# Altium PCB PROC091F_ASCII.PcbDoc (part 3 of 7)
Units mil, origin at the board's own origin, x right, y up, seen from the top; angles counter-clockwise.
Board outline 3590.95 x 906.17 mil, 8 copper layers (Top Layer, GND1, Sig1, PWR1, PWR2, Sig2, GND2, Bottom Layer), stack 63.146 mil thick; 420 components, 316 nets, 1432 pads, 774 vias.
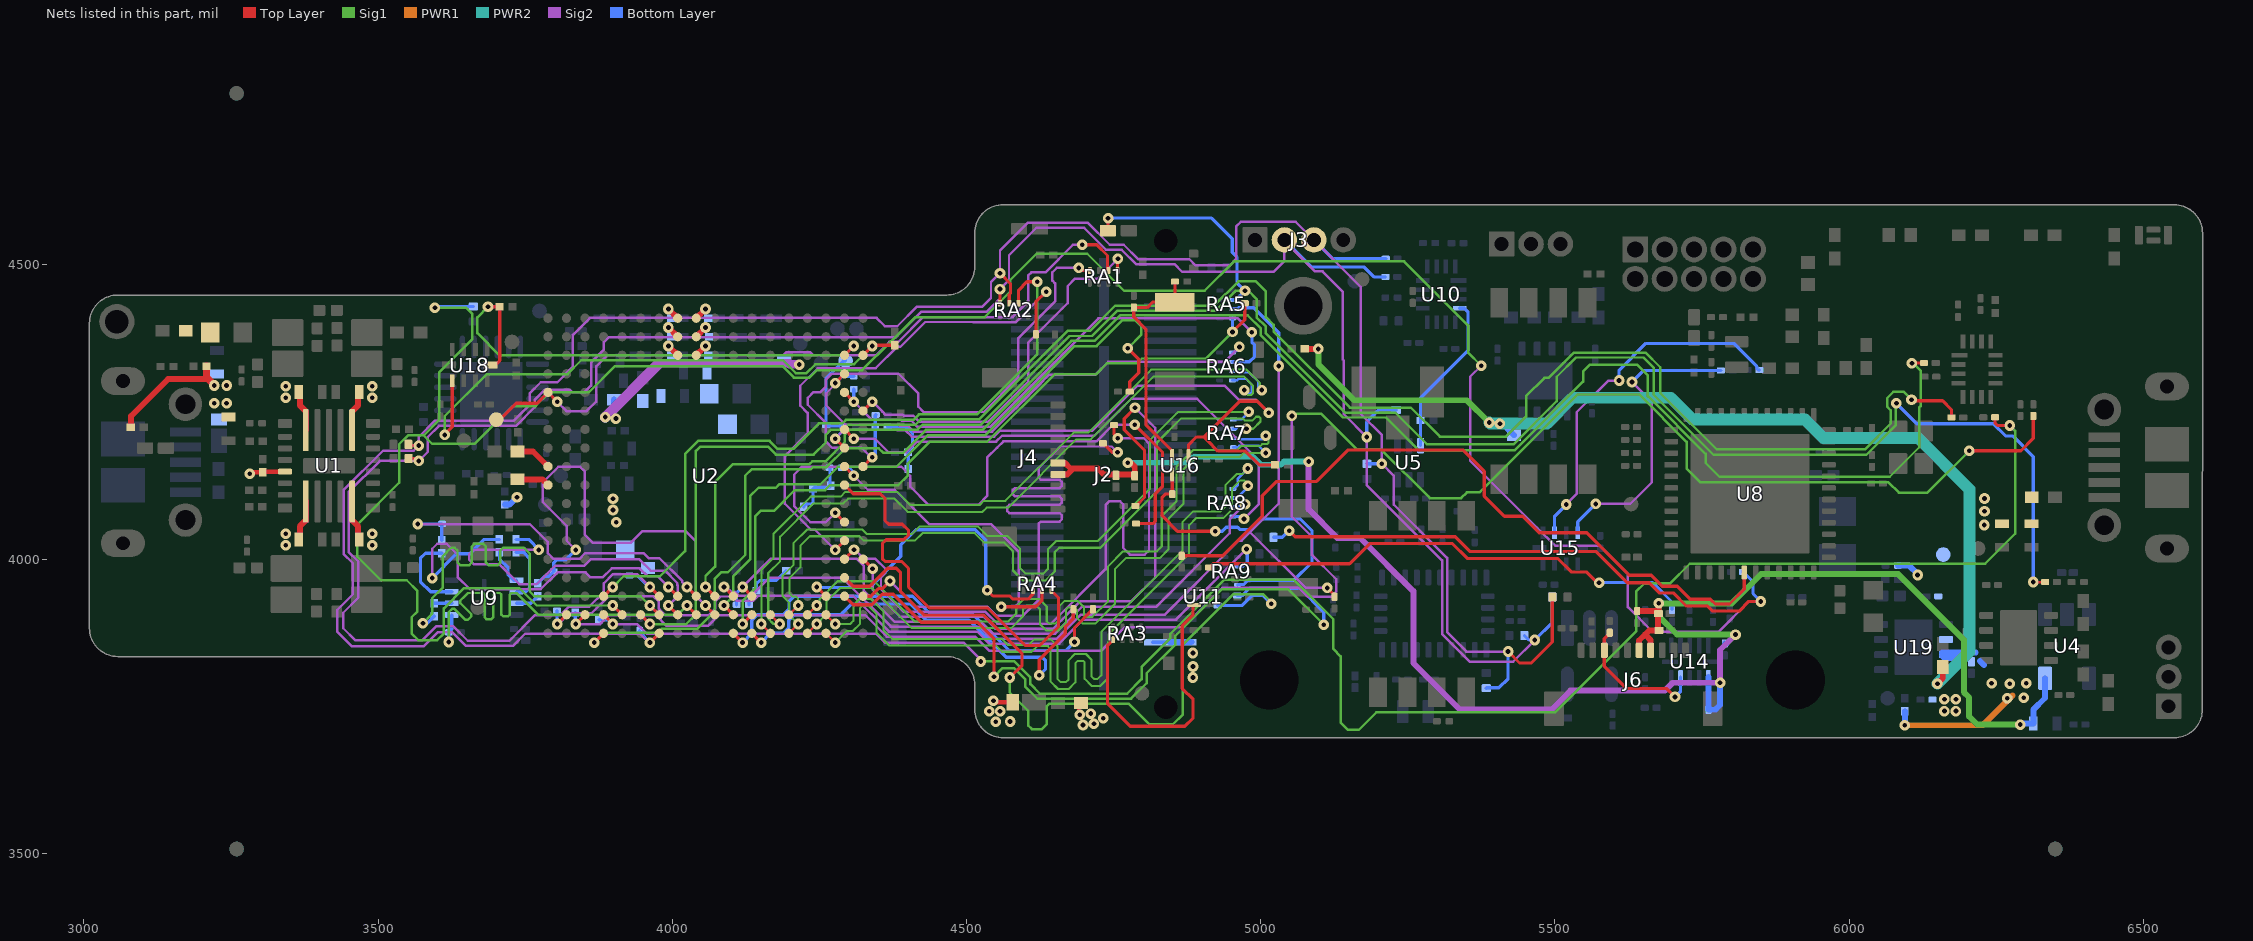
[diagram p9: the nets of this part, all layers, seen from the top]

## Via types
v1: diameter 18, hole 8, Top Layer to Bottom Layer, tented both sides, 737 vias
v2: diameter 19.68, hole 7.87, Top Layer to Bottom Layer, tented both sides, 36 vias
v3: diameter 17, hole 8, Top Layer to Bottom Layer, tented both sides, 1 vias

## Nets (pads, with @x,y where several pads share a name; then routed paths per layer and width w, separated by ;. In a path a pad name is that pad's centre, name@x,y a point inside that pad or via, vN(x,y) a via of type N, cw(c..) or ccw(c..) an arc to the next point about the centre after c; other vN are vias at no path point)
3V0: C7.1 C15.1 C16.1 C115.1 C116.1 C118.1 J4.6 J4.7 J6.6 J6.7 R79.2 R181.2 U4.5 U14.1 | length 3021.3
  Top Layer w10: J4.7@4653.44,4143.81 4671.13,4143.81 4681.23,4153.91 ; J4.6@4653.44,4163.49 J4.6@4655.33,4163.49 4667.18,4163.49 4676.77,4153.91 4681.23,4153.91 ; v1(4774.17,4163.77) 4779.19,4163.77 4785.89,4157.08 4785.89,4142.64 4785.08,4143.44 4733.74,4143.44 4723.27,4153.91 4681.23,4153.91 ; R181.2@5639.79,3911.66 C115.1@5670.49,3911.66 ; J6.6@5643.01,3845.06 5643.01,3861.54 5653.24,3871.77 ; J6.7@5662.69,3842.06 5662.69,3862.32 5653.24,3871.77 ; C115.1@5676.11,3907.2 C115.1@5674.96,3907.2 ; v1(5676.18,3924.73) 5676.18,3908.42 C115.1@5674.96,3907.2 ; 5653.24,3871.77 5660.21,3878.74 5675.67,3878.74 5674.96,3879.45 C115.1@5674.96,3907.2
  Sig1 w10: v1(5806.88,3871.77) 5707.39,3871.77 5676.18,3902.98 v1(5676.18,3924.73) 5800.43,3924.73 5850.17,3974.46 6083.34,3974.46 6195,3862.8 6195,3773.9 6203.8,3765.1 6203.8,3732.72 6217.72,3718.79 v1(6290.97,3718.79)
  PWR2 w10: v1(4774.17,4163.77) 4876.32,4163.77 4886.45,4173.91 4986.43,4173.91 4999.95,4160.4 5034.48,4160.4 5039.83,4165.74 v1(5081.47,4165.74)
  Sig2 w10: v1(5081.47,4165.74) 5081.47,4084.56 5130.11,4035.92 5168.92,4035.92 5259.37,3945.46 5259.37,3823.46 5338.37,3744.46 5494.41,3744.46 5526.41,3776.46 5686.78,3776.46 5700.1,3789.79 v1(5780.63,3789.79) 5780.63,3845.63 v1@5806.82,3871.82
  Bottom Layer w10: U14.1@5760.73,3799.77 5760.73,3764.35 5760.69,3764.32 C118.1@5760.69,3743.88 5772.53,3743.88 5780.63,3751.98 v1(5780.63,3789.79) ; R79.2@5788.67,3856.48 5791.58,3856.48 v1(5806.88,3871.77) ; v1(6290.97,3718.79) 6292.97,3720.79 C7.1@6312.97,3720.79 6312.97,3743.97 6332.97,3763.97 U4.5@6332.97,3797.49
5V_HD_IN: C128.1 J2.2 R20.1 U19.8 | length 106.4
  Bottom Layer w6: J2.2@4816.76,3859.07 J2.2@4846.16,3859.07
  Bottom Layer w10: J2.2@4846.16,3859.07 J2.2@4882.13,3859.07 ; R20.1@6082.89,3988.94 6102.24,3988.94 6116.23,3974.95 v1(6116.23,3973.04)
  other v1: 6161.94,3741.7 6181.41,3741.74 6161.94,3761.63 6181.41,3761.68 4884.84,3798.74 4885,3817.45 4884.84,3840.39
5V_IN: C1.2 C4.1 C30.1 C50.1 C51.1 C52.1 C53.1 D1.1 D2.1 FL3.2 FL12.2 R39.1 R50.2 R64.1 R107.1 U1.9 U1.13 U1.18 U1.22 U1.26 | length 2301.2
  Top Layer w8: v1(3282,4145) 3284.5,4147.5 C30.1@3304,4147.5 3305.18,4148.68 U1.18@3341.81,4148.68 ; v1@4551.43,3756.69 4551.24,3756.88 D2.1@4578.64,3756.88
  Top Layer w10: R39.1@3079.65,4222.86 3080.01,4222.86 3080.01,4242.86 3142.95,4305.8 3209.86,4305.8 ; C52.1@3367.11,4033.27 3367.11,4055.68 3377.24,4065.81 U1.22@3377.24,4097.89 ; C51.1@3367.11,4283.77 3367.11,4261.36 3377.24,4251.23 U1.13@3377.24,4219.15 ; U1.26@3455.98,4097.89 3455.98,4065.81 3466.11,4055.68 C53.1@3466.11,4033.27 ; U1.9@3455.98,4219.15 3455.98,4251.23 3466.11,4261.36 C50.1@3466.11,4283.77 ; R107.1@5074.64,4357.18 v1@5098.17,4357.18 ; v1(5098,4357.17) v1@5098.15,4357.17 ; v1(6150,3788) 6159,3797 FL3.2@6159,3816.31
  Top Layer w12: R50.2@3208.43,4327.73 3208.43,4309.08 v1@3222.57,4294.93
  Sig1 w10: v1(5098,4357.17) 5098,4331 5159,4270 5350.21,4270 v1(5388.21,4232)
  PWR2 w20: v1(5388.21,4232) 5389.98,4230.23 v1(5406.56,4230.23) 5486,4230.23 5529.77,4274 5697,4274 5734,4237 5925,4237 5956,4206 6117,4206 6204.39,4118.61 6204.39,3842.39 v1(6150,3788)
  Bottom Layer w10: R64.1@3715.38,4092.76 3723.59,4092.76 v1(3736.09,4105.26) ; v1@5408.87,4232 FL12.2@5430.41,4210.46
  other v1: 4549.8,3723.5 4574.04,3724.04 4557.1,3741.4 4538.79,3741.55 4545.8,3759.4 3343.32,4023.52 3489.9,4023.52 3343.32,4043.02 3489.9,4043.02 3221.57,4264.93 3242.57,4264.93 3343.32,4274.02 3489.9,4274.02 3343.32,4293.52 3489.9,4293.52 3221.57,4294.93 3242.57,4294.93
5V_IN_B: C42.2 C122.1 C127.1 FL14.2 TP4.1 U19.6
  other v1: 6229.39,4058 6230,4081.54 6230,4103
5V_IN_SW: C129.1 FL11.1 R27.1 U19.7 | length 387.8
  Top Layer w6: v1@4691.08,3733.43 FL11.1@4691.08,3755.5
  PWR1 w10: v1(6094.58,3717.68) 6227.1,3717.68 6277.87,3768.45
  Bottom Layer w10: v1(6094.58,3717.68) R27.1@6094.58,3741.52 ; U19.7@6157.3,3840.2 6158.2,3841.1 6198.3,3841.1 ; U19.7@6157.5,3836.1 6162.01,3831.6 6191.4,3831.6 6186.3,3836.69 U19.7@6161.94,3836.69 ; 6200,3839.4 6198.3,3841.1 ; 6215.1,3841.1 6198.3,3841.1 ; 6222.1,3826.76 6228.92,3819.94
  other v1: 4698.06,3717.99 4716.52,3720.32 4732.55,3729.58 4692.44,3735.48 4711.02,3737.49 6268.5,3763.5 6296.5,3764.5 6273,3788 6242,3789 6301,3789
ALERT: R38.1 U5.3 U10.4 | length 277.2
  Bottom Layer w5.5: U5.3@5271.66,4192.9 R38.1@5271.66,4235.46 5271.66,4274.01 5352.46,4354.8 5352.46,4419.82 5346.17,4426.11 U10.4@5338.3,4426.11
AR_1P0_RF1: C78.1 C79.1 C80.1 C81.1 L12.2 U2.J16 U2.J17 U2.J18 | length 66.8
  Top Layer w10: U2.J16@4040.73,4346.33 v1(4056.48,4362.08) ; U2.J17@4040.73,4377.83 v1(4056.48,4393.58) ; U2.J18@4040.73,4409.33 v1(4056.48,4425.07)
AR_1P0_RF2: C82.1 C83.1 C84.1 C85.1 FL1.1 L14.2 U2.H16 U2.H17 U2.H18 | length 66.8
  Top Layer w10: v1(3993.49,4362.08) U2.H16@4009.24,4346.33 ; v1(3993.49,4393.58) U2.H17@4009.24,4377.83 ; v1(3993.49,4425.07) U2.H18@4009.24,4409.33
AR_1P2: FL6.1 L13.2
AR_1V4_APLL: C90.1 U2.A10 | length 62.3
  Top Layer w10: C90.1@3737.06,4182.85 3763.27,4182.85 U2.A10@3788.76,4157.36
AR_1V4_SYNTH: C89.1 U2.A9 | length 55.5
  Top Layer w10: C89.1@3737.19,4135.45 3779.18,4135.45 U2.A9@3788.76,4125.86
AR_1V8: FL8.1 FL9.1 FL10.1 L11.2 | length 404.6
  Sig2 w15: 3975.42,4330.59 3976.08,4331.25 ; 3976.08,4332.75 4199.24,4332.75 ; 4199.24,4331.25 4199.33,4331.16 4215.39,4331.16 v1(4215.96,4330.59)
  Sig2 w18: v1(3886.15,4241.31) 3975.42,4330.59
  Bottom Layer w10: v1(3886.15,4241.31) 3888.61,4241.31 3901,4253.7 FL9.1@3901,4271
  other v1: 3904.64,4062.7 3899.25,4083.38 3899.25,4102.38 3904.29,4238.76
AR_BSS_LOGGER: RA2.2 U2.D3 | length 1197.9
  Top Layer w5.5: U2.D3@3883.25,3936.89 v1(3899,3952.63) ; RA2.2@4588.48,4434.82 4588.48,4456.94 4602.74,4471.2 v1(4620,4471.2)
  Sig1 w4.2: v1(3899,3952.63) 3917.29,3970.92 3979.16,3970.92 4021.78,4013.55 4021.78,4178.81 4043.81,4200.84 4165.39,4200.84 4179.07,4187.16 4205.95,4187.16 4249.28,4230.49 4288.94,4230.49 4295.15,4236.7 4409.94,4236.7 4419.12,4245.88 4517.88,4245.88 4620,4348 v1(4620,4471.2)
AR_CS1: R9.2 R139.2 U2.C2 | length 3331.6
  Top Layer w5.5: v1(3836.01,3889.64) U2.C2@3851.76,3905.39 ; v1(6204,4184) 6292,4184 6313,4205 R139.2@6313,4242.98
  Sig1 w4.2: v1(5053,4243.3) 5057,4247.3 5102.7,4247.3 5164.32,4185.68 5205.42,4185.68 5287.4,4103.7 5340.7,4103.7 5350.29,4113.29 5371.69,4113.29 5538.09,4279.7 5643.45,4279.7 5723.89,4199.26 5723.89,4154.03 5747.43,4130.49 6066.87,4130.49 6084.43,4112.93 6132.93,4112.93 v1(6204,4184)
  Sig2 w4.2: v1(3836.01,3889.64) 3877.36,3889.64 3892.66,3904.94 3972.04,3904.94 3990.46,3886.52 4060.75,3886.52 4079.18,3904.94 4328.02,3904.94 4364.57,3868.39 4514.72,3868.39 4539.2,3843.9 4728.57,3843.9 4768.67,3884 4868,3884 4935,3951 5064.76,3951 5080.06,3935.7 5119.48,3935.7 5128.45,3944.66 5128.45,3965.78 5087,4007.23 5087,4038 5053,4072 v1(5053,4243.3)
  Bottom Layer w5.5: R9.2@3835,3909.17 3835,3890.65 v1(3836.01,3889.64)
AR_CS1_60PIN: RA3.1 U11.3 | length 486.5
  Top Layer w5.5: RA3.1@4749.31,3863.01 4739.81,3853.51 4739.81,3754.36 4778.08,3716.09 4871.09,3716.09 4885,3730 4885,3761.65 4866.65,3780 4866.65,3886.76 4884.99,3905.09 U11.3@4884.99,3921.94
AR_CS1_BT: R105.2 U8.30 | length 1222.9
  Top Layer w5.5: R105.2@4865.78,4005.59 4935.59,4005.59 5002.56,4072.56 5002.56,4107.46 5027.1,4132 5094.9,4132 5148.45,4185.56 5343.25,4185.56 5379.8,4149.01 5379.8,4107.15 5414.23,4072.71 5445.66,4072.71 5473.46,4044.92 5554.09,4044.92 5626.54,3972.46 5663.74,3972.46 5682.22,3953.98 5707.75,3953.98 5730.02,3931.71 5764.22,3931.71 5772.3,3923.63 5796.62,3923.63 5821.73,3948.74 U8.30@5821.73,3977.25
AR_CS1_LCD: R76.2 R106.2 | length 857.3
  Top Layer w5.5: R106.2@4912.37,3985.56 4918.93,3992.13 5151.04,3992.13 5185.33,4026.43 5325.91,4026.43 5351.12,4001.21 5504.41,4001.21 5527.37,3978.25 5553.48,3978.25 5571.73,3960 v1(5575,3960)
  Bottom Layer w5.5: v1(5575,3960) 5666.02,3960 5698.97,3927.05 R76.2@5698.97,3914.47
AR_CS1_LCD_T: J6.3 R183.1 U14.4 | length 239.1
  Top Layer w5.5: R183.1@5593.19,3873.82 5583.95,3864.58 J6.3@5583.95,3845.06 5583.95,3818.24 5622.3,3779.89 5689.95,3779.89 v1(5704.03,3765.81)
  Bottom Layer w5.5: v1(5704.03,3765.81) 5713.48,3775.26 U14.4@5713.48,3797.8 U14.4@5713.48,3799.77
AR_DMM_CLK: R11.1 U2.U3 | length 1270.4
  Top Layer w5.5: U2.U3@4292.7,3936.89 4307.32,3922.26 4338.99,3922.26 4357.08,3940.36 4375.65,3940.36 4423.2,3892.8 4518.93,3892.8 4546.57,3865.15 v1(4546.57,3799.81)
  Sig1 w4.2: v1(4546.57,3799.81) 4561.46,3814.7 4580.9,3814.7 4600.07,3795.53 4600.07,3782.93 4620.19,3762.81 4779.81,3762.81 4806,3789 4806,3806 4855,3855 4855,3869.71 4934.29,3949 5046.57,3949 v1(5107.05,3888.52)
  Bottom Layer w5.5: R11.1@4960.02,3937.94 4968.46,3937.94 4980.77,3950.25 5066.75,3950.25 5107.05,3909.95 v1(5107.05,3888.52)
AR_DMM_SYNC: R10.1 U2.U4 | length 1283.7
  Top Layer w5.5: U2.U4@4292.7,3968.38 4307.32,3953.76 4335.57,3953.76 4366.31,3984.5 4380.6,3984.5 4388,3977.1 4388,3944.27 4427.07,3905.2 4528.29,3905.2 4594.49,3839 4594.49,3819.69 v1(4573.55,3798.74)
  Sig1 w4.2: v1(4573.55,3798.74) 4573.55,3773.45 4605,3742 4605,3717 4611,3711 4628,3711 4636,3719 4636,3749.41 4641,3754.41 4775.59,3754.41 4810.94,3719.06 4850.56,3719.06 4867.66,3736.15 4867.66,3854.66 4953.6,3940.6 5004,3940.6 5018,3926.6 v1(5018,3924)
  Bottom Layer w5.5: R10.1@4927.02,3921 4967.78,3921 4985.53,3938.75 5003.25,3938.75 v1(5018,3924)
AR_DP0: R88.1 U2.U7 | length 1102
  Top Layer w5.5: v1(4276.95,4078.62) U2.U7@4292.7,4062.87 ; v1(4786.14,4228.21) 4833.25,4181.1 4833.25,4123.66 4820.91,4111.32 4820.91,4064.23 4817.01,4060.33 R88.1@4789.21,4060.33
  Sig2 w4.2: v1(4276.95,4078.62) 4261.23,4062.89 4234.4,4062.89 4207.08,4090.21 4207.08,4100.94 4207.08,4111.59 4207.08,4143.33 4220.78,4157.04 4389.09,4157.04 4404.46,4141.67 4404.46,4123.28 4435.52,4092.22 4519.97,4092.22 4535.14,4107.38 4535.14,4172.74 4551.69,4189.3 4551.95,4189.3 4562.68,4200.02 4721.12,4200.02 4749.31,4228.21 v1(4786.14,4228.21)
AR_DP1: R130.1 U2.U6 | length 924.9
  Top Layer w5.5: v1(4276.95,4015.63) U2.U6@4292.7,4031.37 ; R130.1@4617.95,4383.18 4617.95,4437.33 4635.19,4454.56 v1(4635.35,4454.4)
  Sig2 w4.2: v1(4276.95,4015.63) 4242.74,4049.83 4235.58,4049.83 4191.3,4094.11 4191.3,4175.11 4230,4213.81 4230,4248.45 4217.54,4260.92 4217.54,4294.54 4247.25,4324.25 4345.44,4324.25 4381.77,4360.58 4387.52,4360.58 4429.85,4402.91 4475.18,4402.91 4511.29,4402.91 4511.35,4402.85 4583.81,4402.85 v1(4635.35,4454.4)
AR_DP2: R132.1 U2.V5 | length 1098.3
  Top Layer w5.5: U2.V5@4324.64,3999.43 v1(4340.39,3983.68) ; v1(4786.37,4257.18) 4768.03,4238.84 4768.03,4219.51 4802.49,4185.05 4802.49,4104.7 R132.1@4788.36,4090.57
  Sig2 w4.2: v1(4340.39,3983.68) 4340.39,3948.49 4386.9,3901.99 4528.64,3901.99 4548.94,3881.69 4646.96,3881.69 4694,3928.72 4780.31,3928.72 4820.7,3969.11 4820.7,4222.85 v1(4786.37,4257.18)
AR_DP3: R133.1 U2.U5 | length 1103.4
  Top Layer w5.5: U2.U5@4293.15,4000.33 v1(4308.9,4016.07) ; R133.1@4750.69,4227.63 4750.69,4211.75 v1(4756.94,4205.49)
  Sig2 w4.2: v1(4308.9,4016.07) 4310.02,4016.07 4325.77,4000.33 4345.39,4000.33 4362,3983.71 4362,3976.46 4354.7,3969.16 4354.7,3949.12 4393.43,3910.39 4532.11,3910.39 4552.41,3890.09 4643.49,3890.09 4736.28,3982.88 4736.28,4091.85 4742.4,4097.98 4761.3,4097.98 4766.06,4093.22 4766.06,4019.21 4777.65,4007.61 4802.88,4007.61 4810.15,4014.88 4810.15,4196.59 4801.24,4205.49 v1(4756.94,4205.49)
AR_DP4: R135.1 U2.V3 | length 1157.1
  Top Layer w5.5: U2.V3@4324.2,3936.89 4337.35,3936.89 4350.32,3949.86 4357.03,3949.86 v1(4370,3962.82) ; R135.1@4732.07,4196.8 4747.41,4181.46 v1(4756.8,4181.46)
  Sig2 w4.2: v1(4370,3962.82) 4414.04,3918.79 4535.59,3918.79 4550.54,3903.84 4595.78,3903.84 4622.63,3930.69 4622.63,4029.66 4622.63,4060.28 4626.18,4063.83 4658.3,4063.83 4661.85,4067.38 4661.85,4074.48 4658.3,4078.03 4622.63,4078.03 4572.87,4078.03 4569.32,4081.58 4569.32,4088.68 4572.87,4092.23 4622.63,4092.23 4658.15,4092.23 4661.7,4095.78 4661.7,4102.88 4658.15,4106.43 4622.63,4106.43 4582.47,4106.43 4578.92,4109.98 4578.92,4117.08 4582.47,4120.63 4622.63,4120.63 4658.3,4120.63 4661.85,4124.18 4661.85,4131.28 4658.3,4134.83 4626.18,4134.83 4622.63,4138.38 4622.63,4141.93 4622.63,4154.35 4659.61,4191.33 4746.93,4191.33 v1(4756.8,4181.46)
AR_DP5: R137.1 U2.M1 | length 745.7
  Top Layer w5.5: U2.M1@4135.22,3873.89 v1(4150.97,3858.15) ; v1(4623.77,3802.58) 4623.77,3829.27 4667.89,3873.39 4667.89,3884.63 4681.54,3898.29 R137.1@4681.54,3914.69
  Bottom Layer w5.5: v1(4150.97,3858.15) 4166.72,3873.9 4176.3,3873.9 4176.39,3873.99 4188.95,3873.99 4198.11,3883.16 4198.11,3895.93 4207.67,3905.49 4286.39,3905.49 4304.8,3923.9 4404.12,3923.9 4431.61,3896.41 4504.41,3896.41 4567.49,3833.32 4628.48,3833.32 4634.4,3827.4 4634.4,3813.21 v1(4623.77,3802.58)
AR_DP6: R138.1 U2.L2 | length 1153.9
  Top Layer w5.5: v1(4087.98,3921.14) U2.L2@4103.72,3905.39 ; v1(4774.14,4358.34) 4792.59,4339.89 4792.59,4316.78 4777.4,4301.59 R138.1@4777.4,4284.46
  Sig1 w4.2: v1(4087.98,3921.14) 4103.28,3936.44 4103.28,3970.27 4132.4,3999.39 4132.4,4107 4146.71,4121.31 4176,4121.31 4181.7,4127.01 4251.5,4127.01 4281.4,4156.91 4380.91,4156.91 4434.86,4210.86 4532.1,4210.86 4683.32,4362.08 4720.96,4362.08 4764.48,4405.6 4787.14,4405.6 4797.34,4395.41 4797.34,4381.53 v1(4774.14,4358.34)
AR_DP7: R140.1 U2.L1 | length 752
  Top Layer w5.5: U2.L1@4103.72,3873.89 v1(4119.47,3858.15) ; v1(4683.56,3859.2) 4683.56,3883.42 R140.1@4714.81,3914.68
  Bottom Layer w5.5: v1(4119.47,3858.15) 4135.23,3873.9 4135.23,3896.22 4144.4,3905.39 4188.85,3905.39 4198.31,3914.85 4198.31,3927.62 4207.48,3936.79 4408.21,3936.79 4437.09,3907.91 4509.17,3907.91 4572.26,3844.82 4669.18,3844.82 v1(4683.56,3859.2)
AR_GPIO_0: R66.1 RA5.8 U2.M2 | length 1247.4
  Top Layer w5.5: v1(4119.47,3889.64) U2.M2@4135.22,3905.39 ; v1(4952,4386) 4972.88,4406.88 R66.1@4972.88,4434.77
  Sig1 w4.2: v1(4119.47,3889.64) 4119.47,3928.77 4140.8,3950.1 4140.8,4072.57 4150.14,4081.91 4172.91,4081.91 4208.14,4117.14 4259.64,4117.14 4268.36,4125.86 4384.06,4125.86 4400.5,4142.3 4400.5,4162.2 4437.86,4199.56 4535.36,4199.56 4649.8,4314 4719.9,4314 4738.7,4332.8 4789.7,4332.8 4797.8,4340.9 4906.9,4340.9 v1(4952,4386)
  Bottom Layer w5.5: v1(4952,4386) 4952,4408.75 RA5.8@4952.34,4409.09
AR_GPIO_1: R129.2 RA5.7 U2.L3 | length 1696.1
  Top Layer w5.5: v1(4087.98,3952.63) U2.L3@4103.72,3936.89 ; v1(5113.15,3951) R129.2@5125.2,3938.94
  Sig2 w4.2: v1(4087.98,3952.63) 4091.71,3952.63 4099.51,3944.84 4105.63,3944.84 4113.14,3937.33 4133.62,3937.33 4164.22,3967.93 4288.79,3967.93 4371.53,3885.19 4521.68,3885.19 4541.98,3864.89 4653.92,3864.89 4694.64,3905.61 4837.03,3905.61 4962.72,4031.3 4967.81,4031.3 4982.07,4045.57 ; v1@5030.5,4328.13 5030.5,4093.99 4982.07,4045.57 ; v1(5113.15,3951) 5076.64,3951 4982.07,4045.57
  Bottom Layer w5.5: RA5.7@4952.34,4424.84 4953.03,4425.54 4960.71,4425.54 4962.27,4427.09 4988.12,4427.09 5030.72,4384.49 v1(5030.72,4328.13)
AR_GPIO_2: LD3.1 R115.1 RA5.6 U2.K3 | length 3607.2
  Top Layer w4.2: v1(6312.97,3961) R115.1@6332.97,3961
  Top Layer w5.5: v1(4056.48,3952.63) U2.K3@4072.23,3936.89 ; LD3.1@4740.42,4558.15 4740.42,4579.31 v1(4740.56,4579.45)
  Sig1 w4.2: v1(4056.48,3952.63) 4056.48,3971.07 4072.68,3987.27 4072.68,4131.08 4102.91,4161.31 4233.07,4161.31 4237.92,4166.16 4260.14,4166.16 4293.15,4199.16 4293.15,4210.94 4302.11,4219.9 4314.79,4219.9 4416.9,4219.9 4425.61,4228.61 4524.36,4228.61 4674.89,4379.13 4713.09,4379.13 4756.36,4422.4 4924.28,4422.4 4958.04,4456.16 v1(4973.31,4456.16) 4978.84,4456.16 4993,4442 4993,4410.84 5008.7,4395.14 5008.7,4383.67 5143.37,4249 5228.6,4249 5282.1,4195.5 5430.13,4195.5 5503,4268.37 5503,4309.88 5535.72,4342.6 5650.52,4342.6 5667.56,4325.56 5667.56,4279.35 5769.91,4177 6029,4177 6079.07,4227.07 6079.07,4265.93 v1(6080.37,4264.63)
  Bottom Layer w5.5: v1(4740.56,4579.45) 4916.49,4579.45 4951.75,4544.19 4951.75,4521.43 4959.61,4513.57 4959.61,4469.87 v1(4973.31,4456.16) 4957.74,4440.59 RA5.6@4952.34,4440.59 ; v1@6079.07,4265.93 v1(6080.37,4264.63) 6115,4230 6244.9,4230 6265.65,4209.25 6277.75,4209.25 6312.97,4174.03 v1(6312.97,3961)
AR_HOSTINTR1: R3.1 RA9.6 U2.B2 | length 1425.4
  Top Layer w5.5: v1(3804.51,3889.64) U2.B2@3820.26,3905.39
  Sig2 w4.2: v1(3804.51,3889.64) 3806.53,3889.64 3824.85,3907.96 3862.94,3907.96 3892.18,3937.2 3967.57,3937.2 3977.29,3927.47 3977.29,3915.77 3978.19,3914.88 3978.19,3914.8 3988.05,3904.94 4061.92,3904.94 4072.68,3915.7 4072.68,3927.47 4081.64,3936.44 4102.15,3936.44 4109.66,3928.93 4137.13,3928.93 4145.53,3937.33 4307.51,3937.33 4368.05,3876.79 4518.2,3876.79 4538.5,3856.49 4657.4,3856.49 4698.12,3897.21 4856.21,3897.21 v1(4976,4017)
  Bottom Layer w5.5: R3.1@3804.15,3912.76 3804.15,3890 v1(3804.51,3889.64) ; RA9.6@4960.68,3987.64 4969.78,3987.64 4977,3994.85 4977,4016 v1(4976,4017)
AR_LVDS_0_N: RA6.7 U2.N1 | length 1235.7
  Top Layer w4: v1(4150.97,3889.64) U2.N1@4166.72,3873.89
  Sig1 w3.5: v1(4150.97,3889.64) 4151.55,3890.22 4151.55,3981.11 4171.69,4001.25 4171.69,4042.71 4235.17,4106.2 4286.1,4106.2 4294.1,4114.2 4382.36,4114.2 4404.66,4091.9 4522.5,4091.9 4529.55,4098.95 4566.09,4098.95 4682.04,4214.9 4706.68,4214.9 4813.68,4321.9 4975.86,4321.9 4998.34,4299.42 4998.34,4290.64 v1(5001.79,4287.19)
  Bottom Layer w4: RA6.7@4951.92,4319.52 4959.91,4319.52 4962.29,4317.15 4979.99,4317.15 4995.79,4301.35 4995.79,4293.19 v1(5001.79,4287.19)
AR_LVDS_0_P: RA6.8 U2.N2 | length 1235.8
  Top Layer w4: U2.N2@4166.72,3905.39 v1(4182.46,3889.64)
  Sig1 w3.5: v1(4182.46,3889.64) 4172.11,3889.64 4163.08,3898.67 4163.08,3976.39 4183.19,3996.49 4183.19,4037.94 4239.94,4094.7 4290.86,4094.7 4298.86,4102.7 4377.6,4102.7 4399.9,4080.4 4527.2,4080.4 4534.25,4087.45 4570.85,4087.45 4686.8,4203.4 4711.45,4203.4 4818.45,4310.4 4971.1,4310.4 4986.84,4294.66 4986.84,4281.78 4983.61,4278.54 4978.47,4278.54 4971.79,4285.21 v1(4971.79,4287.19)
  Bottom Layer w4: RA6.8@4951.92,4303.77 4959.91,4303.77 4962.29,4306.15 4975.44,4306.15 4984.79,4296.79 4984.79,4284.28 4981.66,4281.15 4981.39,4280.86 4978.13,4280.86 v1(4971.79,4287.19)
AR_LVDS_1_N: RA7.5 U2.P1 | length 1236.9
  Top Layer w4: U2.P1@4198.21,3873.89 v1(4213.96,3889.64)
  Sig1 w3.5: v1(4213.96,3889.64) 4198.21,3905.39 4198.21,3926.53 4187.47,3937.27 4187.47,3971.89 4206.2,3990.62 4206.2,4027.46 4229.08,4050.35 4322.62,4050.35 4330.06,4042.9 4407.6,4042.9 4420.41,4055.71 4519.06,4055.71 4535.16,4039.6 4569.26,4039.6 4590.61,4018.26 4590.61,3985.36 4600.71,3975.25 4630.15,3975.25 4638.51,3983.61 4638.51,4016.74 4652.59,4030.82 4723.05,4030.82 4812.2,4119.96 4812.2,4202.86 4859.61,4250.28 4979.65,4250.28 v1(4979.65,4250.36)
  Bottom Layer w4: RA7.5@4953.34,4237.27 4967.43,4237.27 4979.65,4249.49 v1(4979.65,4250.36)
AR_LVDS_1_P: RA7.6 U2.P2 | length 1238.7
  Top Layer w4: U2.P2@4198.21,3905.39 v1(4213.96,3921.14)
  Sig1 w3.5: v1(4213.96,3921.14) 4213.96,3932.73 4210.37,3936.32 4204.69,3936.32 4198.97,3942.04 4198.97,3967.13 4217.7,3985.85 4217.7,4022.7 4233.85,4038.85 4317.85,4038.85 4325.3,4031.4 4412.36,4031.4 4425.17,4044.21 4514.29,4044.21 4530.4,4028.1 4564.5,4028.1 4579.11,4013.49 4579.11,3980.59 4595.95,3963.75 4634.92,3963.75 4650.01,3978.85 4650.01,4011.97 4657.35,4019.32 4727.82,4019.32 4823.7,4115.2 4823.7,4198.1 4864.38,4238.78 4970.01,4238.78 4973.38,4235.41 4985.84,4235.41 4992.32,4241.88 4997.31,4241.88 4999.56,4239.63 4999.56,4233.89 4987.2,4221.53 v1(4975.73,4221.53) v1@4975.73,4221.61
  Bottom Layer w4: RA7.6@4953.34,4221.53 4958.16,4221.53 4962.91,4226.27 4970.98,4226.27 v1(4975.73,4221.53)
AR_LVDS_CLK_N: RA7.7 U2.R2 | length 1236.7
  Top Layer w4: U2.R2@4229.71,3905.39 v1(4245.46,3921.14)
  Sig1 w3.5: v1(4245.46,3921.14) 4250.5,3926.18 4250.5,3932.09 4280.77,3962.36 4343.54,3962.36 4411.66,3894.25 4571.32,3894.25 4584.54,3907.46 4584.54,3919.41 4597.67,3932.55 4623.26,3932.55 4636.4,3919.42 4636.4,3894.34 4640.5,3890.23 4650.74,3890.23 4657.7,3897.19 4657.7,3919.66 4667,3928.97 4688.58,3928.97 4699.67,3917.88 4699.67,3904.32 4702.3,3901.69 4714,3901.69 4740.68,3928.37 4740.68,3987.7 4765.98,4013 4823.52,4013 4831.85,4021.33 4831.85,4073.27 4856.96,4098.38 4856.96,4157.06 4885.22,4185.33 4960.01,4185.33 4966.58,4191.9 4998.96,4191.9 5002.41,4195.35 5010.84,4195.35 5013.13,4197.64 5013.13,4204.87 v1(5008.6,4209.4)
  Bottom Layer w4: RA7.7@4953.34,4205.78 4961.34,4205.78 4963.72,4203.4 4992.27,4203.4 ; 4992.28,4203.4 5002.6,4203.4 v1(5008.6,4209.4)
AR_LVDS_CLK_P: RA7.8 U2.R1 | length 1235.6
  Top Layer w4: U2.R1@4229.71,3873.89 v1(4245.46,3889.64)
  Sig1 w3.5: v1(4245.46,3889.64) 4262,3906.19 4262,3927.33 4285.53,3950.86 4338.78,3950.86 4406.89,3882.75 4576.09,3882.75 4596.04,3902.7 4596.04,3914.65 4602.44,3921.05 4618.5,3921.05 4624.9,3914.65 4624.9,3889.58 4635.74,3878.73 4655.5,3878.73 4669.2,3892.43 4669.2,3914.37 4672.29,3917.47 4683.82,3917.47 4688.17,3913.11 4688.17,3899.56 4697.54,3890.19 4718.77,3890.19 4752.18,3923.6 4752.18,3982.94 4770.75,4001.5 4828.29,4001.5 4843.35,4016.56 4843.35,4068.5 4868.46,4093.61 4868.46,4152.3 4889.99,4173.83 4964.78,4173.83 4971.35,4180.4 v1(5008.6,4180.4)
  Bottom Layer w4: RA7.8@4953.34,4190.03 4961.34,4190.03 4963.72,4192.4 4987.72,4192.4 4996.6,4192.4 v1(5008.6,4180.4)
AR_LVDS_FRCLK_N: RA8.5 U2.T2 | length 1234.7
  Top Layer w4: U2.T2@4261.2,3905.39 v1(4276.95,3889.64)
  Sig1 w3.5: v1(4276.95,3889.64) 4302.37,3889.64 4307.79,3895.06 4307.79,3921.8 4318.23,3932.23 4337.81,3932.23 4358.82,3911.22 4358.82,3879.44 4373.94,3864.32 4559.76,3864.32 4570.08,3854 4605.74,3854 4615.24,3863.5 4642.93,3863.5 4654.4,3852.03 4654.4,3796.6 4660.23,3790.77 4668.84,3790.77 4673.44,3795.37 4673.44,3828.02 4684.1,3838.67 4703.01,3838.67 4712.34,3829.34 4712.34,3801.17 4717.6,3795.91 4722.41,3795.91 4729.13,3802.63 4729.13,3876.65 4866.74,4014.26 4866.74,4062.56 4885.24,4081.06 4931.87,4081.06 4939.98,4089.16 4939.98,4125.23 4959.7,4144.96 4969.2,4144.96 v1(4978.15,4153.91)
  Bottom Layer w4: RA8.5@4952.69,4119.49 4954.75,4119.49 4961.25,4126 4961.25,4137.01 v1(4978.15,4153.91)
AR_LVDS_FRCLK_P: RA8.6 U2.T1 | length 1234.2
  Top Layer w4: U2.T1@4261.2,3873.89 v1(4276.95,3858.15)
  Sig1 w3.5: v1(4276.95,3858.15) 4296.95,3878.14 4307.14,3878.14 4319.29,3890.3 4319.29,3917.03 4322.99,3920.73 4333.04,3920.73 4347.32,3906.46 4347.32,3874.68 4369.18,3852.82 4550.24,3852.82 4560.56,3842.5 4610.5,3842.5 4620,3852 4638.16,3852 4642.9,3847.26 4642.9,3791.83 4655.47,3779.27 4673.6,3779.27 4684.94,3790.61 4684.94,3823.25 4688.86,3827.17 4698.24,3827.17 4700.84,3824.58 4700.84,3796.41 4712.84,3784.41 4727.18,3784.41 4740.63,3797.86 4740.63,3871.89 4878.24,4009.49 4878.24,4057.8 4890,4069.56 4936.64,4069.56 4951.48,4084.4 4951.48,4120.47 4964.47,4133.46 4972.45,4133.46 4978.25,4127.66 v1(4978.25,4124.51)
  Bottom Layer w4: RA8.6@4952.69,4103.74 4959.55,4103.74 4978.25,4122.44 v1(4978.25,4124.51)
AR_MCUCLKOUT: RA1.1 U2.V13 | length 645.6
  Top Layer w5.5: U2.V13@4324.2,4251.85 v1(4339.94,4267.59) ; RA1.1@4756.3,4490.32 RA1.1@4756.8,4490.32 4756.8,4509.89 v1(4757.37,4510.46)
  Sig2 w4.2: v1(4339.94,4267.59) 4357,4250.54 4362.44,4245.1 4391.75,4245.1 4393.12,4243.74 4409.56,4243.74 4420.13,4233.16 4536.42,4233.16 4604.57,4301.31 4604.57,4367.63 4672,4435.06 4672,4464.08 4684.7,4476.78 4723.69,4476.78 v1(4757.37,4510.46)
AR_MISO1: R121.2 U2.D1 | length 3090.6
  Top Layer w5.5: v1(3867.5,3858.15) U2.D1@3883.25,3873.89 ; v1@6108.64,4333 6109,4333 6109.23,4333.23 R121.2@6127.22,4333.23
  Sig1 w4.2: v1(3867.5,3858.15) 3884.4,3875.04 3975.37,3875.04 3982.08,3881.75 4042.55,3881.75 4072.59,3911.79 4072.59,3966.9 4083.09,3977.41 4094.31,3977.41 4124,4007.09 4124,4141.74 4134.66,4152.4 4235.06,4152.4 4238.92,4156.26 4262.13,4156.26 4294.27,4188.41 4350.62,4188.41 4358.63,4180.4 4391.83,4180.4 4431.01,4219.57 4527.21,4219.57 4678.37,4370.73 4717.73,4370.73 4761,4414 4977.96,4414 5000.3,4391.66 5000.3,4380.19 5139.89,4240.6 5213,4240.6 5268.9,4184.7 5431.21,4184.7 5548,4301.49 5548,4319 5559,4330 5640,4330 5658,4312 5658,4277.03 5756.18,4178.86 5756.18,4163.67 5779.85,4140 6069.02,4140 6119.07,4190.05 6119.07,4257.8 6121.3,4260.03 6121.3,4320.34 v1@6108.64,4333
  other v1: 6106.64,4333
AR_MOSI1: R128.2 U2.F2 | length 3074.5
  Top Layer w5.5: U2.F2@3946.24,3905.39 v1(3961.99,3889.64) ; v1@6104,4269 v1(6106,4271) 6107.75,4269.25 6158.75,4269.25 6173.9,4254.1 R128.2@6173.9,4240.71
  Sig1 w4.2: v1(3961.99,3889.64) 4023.85,3889.64 4040.28,3906.08 4040.28,3950.8 4040.28,4183.75 4047.75,4191.21 4162.53,4191.21 4176.13,4177.61 4240.1,4177.61 4260.76,4198.26 4260.76,4210.94 4269.72,4219.9 4290.23,4219.9 4298.63,4228.3 4413.42,4228.3 4422.6,4237.48 4521.36,4237.48 4671.41,4387.53 4671.76,4387.88 4709.88,4387.88 4752.8,4430.8 4920.8,4430.8 4961.97,4471.97 4991.75,4471.97 5008.9,4454.83 5008.9,4411.26 5022,4398.16 5022,4387 5151.6,4257.4 5255,4257.4 5304.4,4208 5417,4208 5451,4242 5451,4277.02 5482,4308.02 5489.26,4308.02 5532.24,4351 5654,4351 5679,4326 5679,4282.47 5774.97,4186.5 6026.62,4186.5 6070.67,4230.55 6070.67,4252.69 6064.36,4259 6064.36,4273.36 6075,4284 6093,4284 v1(6106,4271)
AR_MSS_LOGGER: R58.1 R62.2 R131.1 U2.E2 | length 5198.3
  Top Layer w5.5: v1(3899,3921.14) U2.E2@3914.75,3905.39 ; v1(5048.37,4048.33) 5058.78,4037.93 5330.67,4037.93 5355.88,4012.71 5570.03,4012.71 5622.99,3959.75 5660.19,3959.75 5677.46,3942.48 5701.28,3942.48 5723.55,3920.21 5759.46,3920.21 5768.01,3911.66 5813.11,3911.66 5829.44,3928 v1(5850,3928)
  Sig1 w4.2: v1(3596.65,4427.2) 3649.51,4427.2 3660.27,4416.45 3660.27,4373.72 3603.65,4317.11 3603.65,4236.31 3577.64,4210.3 ; v1(3899,3921.14) 3769.66,3921.14 3740,3950.8 3646.32,3950.8 3611.78,3916.26 3611.78,3873.46 3600.32,3861.99 3568.47,3861.99 3557,3873.47 3557,3901.22 3567,3911.22 3567,3945.79 3548.79,3964 3505,3964 3465,4004 3465,4059.02 3535.96,4129.97 3535.96,4195.26 3551,4210.3 3577.64,4210.3 ; v1(5374.72,4328.62) 5352.46,4350.89 5352.46,4397.08 5243.73,4505.8 4954.35,4505.8 4904.55,4456 4768,4456 4705.16,4518.84 4619.07,4518.84 4574.06,4473.83 4574.06,4454.4 4530.98,4411.31 4413.43,4411.31 4372,4369.88 4371.53,4369.88 4322.7,4321.05 4245.78,4321.05 4233.02,4308.29 4206.72,4308.29 4187.01,4328 3902.82,4328 3858,4283.18 3791.2,4283.18 3767.82,4259.8 3727.83,4259.8 3663.79,4195.75 3592.18,4195.75 3577.64,4210.3
  Sig2 w4.2: 5356.11,4218.7 5356.11,4245.3 ; 5356.13,4218.69 5356.13,4166.89 5469.8,4053.21 5500.11,4022.9 5575.81,4022.9 5624.1,3974.62 5624.1,3918.36 5666.26,3876.19 5777.64,3876.19 5829.44,3928 v1(5850,3928) ; 5356.13,4245.31 5356.13,4310.03 v1(5374.72,4328.62)
  Bottom Layer w5.5: v1(3596.65,4427.2) 3598.81,4429.36 R62.2@3662,4429.36 ; R58.1@5021.79,4036.94 5036.79,4036.94 5048.18,4048.33 v1(5048.37,4048.33) ; R131.1@5819.37,3978.41 5836.62,3961.16 5836.62,3941.38 v1(5850,3928)
AR_NERR_OUT: R21.1 RA6.5 U2.U15 | length 899.2
  Top Layer w5.5: v1(4276.95,4299.09) U2.U15@4292.7,4314.84
  Sig2 w4.2: v1(4276.95,4299.09) 4276.95,4297.07 4261.65,4281.77 4261.65,4261.26 4294.61,4228.3 4384.8,4228.3 4386.16,4226.94 4400.1,4226.94 4410.67,4216.36 4543.38,4216.36 4621.37,4294.35 4640.62,4313.6 4719.2,4313.6 4740.85,4335.25 4761.07,4335.25 4938.51,4335.25 v1(4963.86,4360.6)
  Bottom Layer w5.5: v1(4276.95,4299.09) 4288.62,4310.76 R21.1@4308.45,4310.76 ; RA6.5@4951.92,4351.02 4954.28,4351.02 v1(4963.86,4360.6)
AR_NERRIN: R22.1 RA6.6 U2.U14 | length 908.2
  Top Layer w5.5: U2.U14@4292.7,4283.34 v1(4308.45,4267.59)
  Sig2 w4.2: v1(4308.45,4267.59) 4339.34,4236.7 4388.27,4236.7 4389.64,4235.34 4406.08,4235.34 4416.65,4224.76 4539.9,4224.76 4724.04,4408.9 4961.42,4408.9 v1(4985,4385.32)
  Bottom Layer w5.5: v1(4308.45,4267.59) R22.1@4308.45,4288.76 ; RA6.6@4951.92,4335.27 4980.71,4335.27 4989.59,4344.15 4989.59,4363.81 4985,4368.4 v1(4985,4385.32)
AR_NRST: C130.1 R59.1 R108.1 TP14.1 U2.U11 U16.4 | length 1351.6
  Top Layer w5.5: v1(4276.95,4204.6) U2.U11@4292.7,4188.85 ; U16.4@4877.15,4175.21 4877.37,4175.43 4877.37,4194.43 4890.4,4207.46 4903.41,4207.46 ; v1(5013.53,4248.65) 4994.07,4268.11 4964.06,4268.11 4908.95,4213 ; R108.1@5024.3,4159.98 4997.18,4159.98 4973.58,4183.58 4927.3,4183.58 4908.95,4201.93 ; 4903.41,4207.46 4908.95,4201.93 ; 4903.41,4207.46 4908.95,4213 ; 4908.95,4201.93 4908.95,4213
  Sig2 w4.2: v1(4276.95,4204.6) 4292.25,4219.9 4381.32,4219.9 4382.68,4218.54 4396.62,4218.54 4407.19,4207.96 4546.86,4207.96 4557.16,4218.26 4714.15,4218.26 4750.8,4254.91 4750.8,4255.13 4790.1,4294.43 4939.23,4294.43 4963.18,4270.48 4991.7,4270.48 v1(5013.53,4248.65)
  Bottom Layer w5.5: v1(4276.95,4204.6) 4289.15,4216.8 R59.1@4289.15,4223.19 ; R59.1@4290.72,4224.76 R59.1@4289.15,4223.19 ; TP14.1@4294.6,4337.1 4291.1,4337.1 4261.3,4307.3 4261.3,4228.4 C130.1@4261.7,4228 4263.32,4226.38 4286.81,4226.38 4289.15,4224.04 R59.1@4289.15,4223.19
AR_NRST_1: R177.2 RA9.8 U16.1 | length 565.2
  Top Layer w5.5: U16.1@4849.59,4143.71 R177.2@4849.59,4110.46 4837.62,4110.46 4832.41,4105.25 4832.41,4073.43 4858.37,4047.46 v1(4922.74,4047.46)
  Bottom Layer w5.5: v1(4922.74,4047.46) 4935,4047.46 4941.54,4054 4960.76,4054 4964.26,4050.5 4983.79,4050.5 5001.38,4068.09 5067.09,4068.09 5087.12,4048.06 5087.12,3995 5056.12,3964 4978.25,3964 4971.09,3956.83 4961.37,3956.83 RA9.8@4960.68,3956.14
AR_NRST_2: C120.1 R124.1 SW2.1 U16.6 | length 387.8
  Top Layer w5.5: U16.6@4849.59,4175.21 4849.59,4183.68 4804.95,4228.32 4804.95,4390.94 4784.37,4411.52 C120.1@4784.37,4427.45 4806.96,4427.45 4816.38,4436.87 SW2.1@4854.16,4436.87 R124.1@4854.16,4471.7
AR_OSC_CLKOUT: RA1.2 TP17.1 U2.A14 | length 1287.4
  Top Layer w5.5: TP17.1@3701,4237 3706.66,4237 3734.51,4264.85 3770.28,4264.85 U2.A14@3788.76,4283.34 v1(3804.51,4267.59) ; v1(4696.57,4534.14) 4721.4,4534.14 4739.62,4515.92 4739.62,4491.75 RA1.2@4741.05,4490.32
  Sig2 w4.2: v1(3804.51,4267.59) 3804.51,4266.96 3820.08,4251.4 3854.51,4251.4 3870.73,4267.62 3870.73,4327.49 3890.02,4346.78 4188.8,4346.78 4193.92,4351.9 4234,4351.9 4239.12,4346.78 4346.9,4346.78 4357,4356.89 4369.1,4368.98 4384.04,4368.98 4426.37,4411.31 4478.66,4411.31 4514.77,4411.31 4514.83,4411.26 4578.4,4411.26 4604.7,4437.55 4604.7,4481.62 4610.23,4487.15 4633.97,4487.15 4680.96,4534.14 v1(4696.57,4534.14)
AR_PMIC_CLKOUT_SOP2: R85.1 R103.1 RA1.4 U2.V10 | length 994.8
  Top Layer w5.5: U2.V10@4324.2,4157.36 v1(4339.94,4173.11) ; v1(4690.56,4494.86) 4695.1,4490.32 RA1.4@4709.55,4490.32
  Sig2 w4.2: v1(4339.94,4173.11) 4337.92,4173.11 4321.73,4189.3 4271.61,4189.3 4261,4199.91 4261,4231.4 4230.16,4262.25 4230.16,4273.93 4240.02,4283.79 4251.79,4283.79 4261.2,4293.2 4261.2,4304.98 4271.44,4315.22 4384.1,4315.22 4418.24,4281.08 4418.24,4258.82 4427.09,4249.96 4529.46,4249.96 4587.77,4308.27 4587.77,4375 4650.65,4437.88 4650.65,4468.54 4646.07,4473.13 4646.07,4487.37 4653.46,4494.76 4686.25,4494.76 4686.34,4494.86 v1(4690.56,4494.86)
  Bottom Layer w5.5: v1(4339.94,4173.11) 4344.93,4178.09 R85.1@4344.93,4224.99 4344.93,4244.41 R103.1@4345.62,4245.1
AR_QSPI_CLK: R47.1 U2.H2 | length 649.9
  Top Layer w5.5: v1(3993.49,3921.14) U2.H2@4009.24,3905.39
  Sig2 w4.2: v1(3773.02,4015.63) 3662.13,4015.63 3654.68,4008.18 3654.68,3999.45 3663.21,3990.92 3706.39,3990.92 3740.15,3957.16 3769.11,3957.16 3800.25,3988.31 3850.05,3988.31 3861.17,3999.43 3944.27,3999.43 3963.34,3980.36 3987.4,3980.36 4008.79,3958.97 4008.79,3955.94 4008.98,3955.75 4008.98,3936.63 v1(3993.49,3921.14)
  Bottom Layer w5.5: R47.1@3734.37,4033.51 3755.94,4033.51 v1@3774.12,4015.33
AR_QSPI_CLK_T: R47.2 U9.6 | length 102.2
  Bottom Layer w5.5: R47.2@3734.37,4011.47 3747.4,4011.47 3757.25,4001.62 3757.25,3950.78 3750.99,3944.52 U9.6@3735.4,3944.52
AR_QSPI_CS: R43.1 U2.J2 U9.1 | length 773
  Top Layer w5.5: v1(4024.98,3921.14) U2.J2@4040.73,3905.39
  Sig1 w4.2: v1(3620.18,3859.13) 3620.18,3909.8 3625.67,3915.29 3629.69,3915.29 3648.37,3896.61 3652.38,3896.61 3658.41,3902.63 3658.41,3906.65 3639.73,3925.33 3639.73,3929.34 3647.76,3937.38 3652.78,3942.4 3652.87,3942.4 3667.07,3942.4 3678.43,3942.4 3681.27,3939.56 3681.27,3900.87 3684.11,3898.03 3692.63,3898.03 3695.47,3900.87 3695.47,3939.56 3698.31,3942.4 3706.83,3942.4 3709.67,3939.56 3709.67,3905.77 3712.51,3902.93 3721.03,3902.93 3723.87,3905.77 3723.87,3939.56 3726.71,3942.4 3730.97,3942.4 3735.14,3942.4 3771.98,3905.56 4009.4,3905.56 v1(4024.98,3921.14)
  Bottom Layer w5.5: v1(3620.18,3859.13) R43.1@3620.18,3875.43 3625.17,3880.41 U9.1@3625.17,3905.15
AR_QSPI_D0: R6.1 U2.H3 | length 707.5
  Top Layer w5.5: v1(3993.49,3952.63) U2.H3@4009.24,3936.89
  Sig2 w4.2: v1(3592.02,3967.77) 3592.02,4017.53 3600.59,4026.09 3616.46,4026.09 3635.24,4007.31 3635.24,3969.77 3656.25,3948.76 3776.34,3948.76 3804.94,3977.35 3852.64,3977.35 3861.17,3968.83 3881.68,3968.83 3897.15,3984.3 3944.55,3984.3 3957.91,3970.95 3975.17,3970.95 v1(3993.49,3952.63)
  Bottom Layer w5.5: v1(3592.02,3967.77) 3633.25,4009 3656,4009 3680.51,4033.51 R6.1@3706.27,4033.51
AR_QSPI_D0_T: R6.2 U9.5 | length 62.4
  Bottom Layer w5.5: R6.2@3706.27,4011.47 3706.27,3999.75 3720.96,3985.06 3720.96,3973.39 3730.15,3964.2 U9.5@3735.4,3964.2
AR_QSPI_D1: R46.1 U2.G2 | length 721.8
  Top Layer w5.5: v1(3961.99,3921.14) U2.G2@3977.74,3905.39
  Sig1 w4.2: v1(3576.23,3891.02) 3592,3906.8 3592,3933.42 3610.05,3951.47 3610.05,4005.15 3624.12,4019.22 3630.16,4019.22 3635,4014.38 3635,3994.04 3639.84,3989.2 3654.36,3989.2 3659.2,3994.04 3659.2,4019.22 3659.2,4021.32 3664.04,4026.16 3678.56,4026.16 3683.4,4021.32 3683.4,4019.22 3683.4,3994.04 3688.24,3989.2 3702.76,3989.2 3707.6,3994.04 3707.6,4014.38 3712.44,4019.22 3719.7,4019.22 3747.78,4019.22 3757.72,4009.29 3757.72,3944.96 3765.75,3936.93 3946.2,3936.93 v1(3961.99,3921.14)
  Bottom Layer w5.5: v1(3576.23,3891.02) 3583.61,3891.02 R46.1@3595.37,3902.79
AR_QSPI_D1_T: R46.2 U9.2 | length 29.8
  Bottom Layer w5.5: R46.2@3595.37,3924.83 U9.2@3625.17,3924.83
AR_QSPI_D2: R44.1 R48.1 U2.J3 | length 613.8
  Top Layer w5.5: v1(4024.98,3952.63) U2.J3@4040.73,3936.89
  Sig2 w4.2: v1(3567.42,4059.59) 3757.86,4059.59 3788.32,4029.13 3788.32,4010.18 3798.17,4000.33 3842.35,4000.33 3852.2,4010.18 3951.27,4010.18 3959.77,4001.69 3977.95,4001.69 4017.19,3962.45 4017.19,3960.43 v1(4024.98,3952.63)
  Bottom Layer w5.5: v1@3567.42,4059.85 R44.1@3608.37,4059.85 ; R48.1@3608.37,4032.12 R44.1@3608.37,4059.85 ; R44.1@3608.85,4059.85 R44.1@3608.37,4059.85
AR_QSPI_D2_T: R48.2 U9.3 | length 140
  Bottom Layer w5.5: R48.2@3608.37,4010.07 3580.6,4010.07 3572,4001.47 3572,3961.71 3589.2,3944.52 U9.3@3625.17,3944.52
AR_QSPI_D3: R45.1 R49.1 U2.K2 | length 775.9
  Top Layer w5.5: v1(4056.48,3921.14) U2.K2@4072.23,3905.39
  Sig2 w4.2: v1(3836.01,4015.63) 3820.71,4030.93 3820.71,4056.51 3779.9,4097.31 3779.9,4130.18 3806.63,4156.91 3843.24,4156.91 3851.54,4148.61 3851.54,4041.09 3864.63,4027.99 3929.74,4027.99 3949.45,4047.7 4022.42,4047.7 4040.28,4029.84 4040.28,3937.33 v1(4056.48,3921.14)
  Bottom Layer w5.5: R49.1@3771.3,3958.79 3783.11,3970.6 3790.39,3970.6 R45.1@3798.7,3978.91 3798.7,3993.8 3803.85,3998.95 3819.33,3998.95 v1(3836.01,4015.63)
AR_QSPI_D3_T: R49.2 U9.7 | length 40.8
  Bottom Layer w5.5: U9.7@3735.4,3924.83 3759.4,3924.83 R49.2@3771.3,3936.74
AR_RS232RX: R5.2 U2.V16 U18.6 | length 983.2
  Top Layer w5.5: v1@3613.41,4212.05 3626.27,4224.91 U18.6@3626.27,4303.01 ; U2.V16@4324.2,4346.33 v1(4339.94,4362.08) 4341.11,4363.24 R5.2@4378.13,4363.24
  Sig1 w4.2: v1(3613.41,4211.05) 3613.41,4243.04 3684.88,4314.52 3822,4314.52 3845.35,4337.86 4188.04,4337.86 4209.91,4315.99 4228.08,4315.99 4243.29,4331.19 4309.05,4331.19 v1(4339.94,4362.08)
AR_RS232RX_BT: R102.1 U15.4 | length 515.7
  Sig2 w4.2: v1(5569.37,4093.77) 5628,4093.77 5664.77,4130.54 5664.77,4267.23 v1(5631,4301)
  Bottom Layer w5.5: U15.4@5538.73,4044.92 5538.73,4063.13 v1(5569.37,4093.77) ; v1(5631,4301) 5640.41,4310.41 5650.41,4320.41 R102.1@5782.02,4320.41
AR_RS232TX: R4.2 U2.U16 U18.10 | length 866.6
  Top Layer w5.5: v1(3686.89,4429.01) R4.2@3706.52,4429.01 3706.7,4428.83 3706.7,4337.35 3698.93,4329.59 U18.10@3691.23,4329.59 ; U2.U16@4292.7,4346.33 v1(4308.45,4362.08)
  Sig1 w4.2: v1(3686.89,4429.01) 3668.77,4410.89 3668.77,4384.18 3706.68,4346.26 4292.63,4346.26 v1(4308.45,4362.08)
AR_RS232TX_BT: R90.1 U15.2 | length 610.2
  Sig2 w4.2: v1(5519.05,4092.71) 5536.97,4110.64 5536.97,4249.48 5590.96,4303.46 v1(5608.98,4303.46)
  Bottom Layer w5.5: U15.2@5499.36,4044.92 5499.36,4073.03 v1(5519.05,4092.71) ; v1(5608.98,4303.46) 5608.98,4320.91 5654.62,4366.55 5804.07,4366.55 5843.18,4327.44 5843.18,4323.71 5845.6,4321.29 R90.1@5847.4,4321.29
AR_SCL: J3.2 R8.1 R32.1 R51.1 R67.1 R70.2 R99.2 RA2.4 U2.G3 | length 4279.3
  Top Layer w5.5: R32.1@3551.93,4171 3564.93,4171 v1(3569.1,4166.83) ; v1(3961.99,3952.63) U2.G3@3977.74,3936.89 ; v1(4556.94,4458.91) 4556.98,4458.87 RA2.4@4556.98,4434.82
  Sig2 w4.2: v1(3961.99,3952.63) 3940.11,3974.52 3899.25,3974.52 3883.7,3958.97 3883.7,3944.07 3858.84,3919.21 3824.22,3919.21 3809.95,3904.94 3766.68,3904.94 3723.05,3861.32 3652.37,3861.32 3627.68,3886 3599,3886 3575.21,3862.21 3461.14,3862.21 3440.85,3882.5 3440.85,3908.85 3466,3934 3466,3996.25 3449.97,4012.28 3449.97,4113.76 3503.05,4166.83 v1(3569.1,4166.83) 3584.4,4182.13 3584.4,4207.33 3603.42,4226.35 3734.35,4226.35 3766,4258 3766,4270.44 3783.51,4287.95 3825.51,4287.95 3829.67,4283.79 3850.96,4283.79 3861.97,4294.8 3861.97,4334.16 3883.7,4355.89 3883.7,4368.42 3892.66,4377.38 4380.56,4377.38 4423.61,4420.43 4534.67,4420.43 4556.94,4442.7 v1(4556.94,4458.91) 4572.24,4474.21 4572.24,4516.44 4618.8,4563 4699.81,4563 4737.05,4525.76 4763.71,4525.76 4788.17,4501.3 4853.3,4501.3 4866.6,4488 5022,4488 5040.29,4506.29 J3.2@5040.29,4540.85 ; J3.2@5040.29,4542.38 J3.2@5040.29,4540.85 ; v1(5465.87,3862.46) 5429.07,3825.67 5355.06,3825.67 5308.27,3872.46 5308.27,3997.83 5180.09,4126.01 v1(5180.09,4207.42) 5141.3,4246.21 5141.3,4337.34 5139.28,4339.36 5139.28,4454.72 5105.21,4488.79 5092.35,4488.79 J3.2@5040.29,4540.85
  Bottom Layer w5.5: R8.1@3927.41,3972.12 3940.25,3972.12 3959.73,3952.63 v1(3961.99,3952.63) ; J3.2@5040.29,4542.38 5086.17,4496.5 5175.34,4496.5 5192.31,4479.52 R99.2@5212.09,4479.52 ; v1(5180.09,4207.42) 5180.09,4233.18 5200.07,4253.16 R51.1@5230.37,4253.16 ; R70.2@5448.17,3870.14 5455.84,3862.46 v1(5465.87,3862.46) 5495.58,3892.17 R67.1@5495.58,3935.46
AR_SDA: J3.3 R7.1 R28.1 R57.1 R68.1 R71.2 R101.2 RA2.3 U2.G1 | length 4307.7
  Top Layer w5.5: R28.1@3551.59,4193 3569,4193 v1(3569.1,4192.9) ; v1(3961.99,3858.15) U2.G1@3977.74,3873.89 ; v1(4556.94,4486) 4557,4486 4574.69,4468.31 4574.69,4451.56 4572.73,4449.6 RA2.3@4572.73,4434.82 ; v1(5420.37,3842.92) 5439.83,3823.46 5459.89,3823.46 5495.58,3859.15 R68.1@5495.58,3935.46
  Sig2 w4.2: v1(3961.99,3858.15) 3959.97,3858.15 3944.67,3873.45 3750.16,3873.45 3729.32,3852.6 3649.2,3852.6 3625.9,3875.9 3601.9,3875.9 3578,3852 3455.21,3852 3431,3876.21 3431,3914 3457,3940 3457,3993.37 3441.57,4008.8 3441.57,4117.23 3508.43,4184.09 3560.29,4184.09 v1(3569.1,4192.9) 3569.1,4207.7 3596.15,4234.75 3730.32,4234.75 3757.6,4262.04 3757.6,4281.66 3776.54,4300.6 3804.66,4300.6 3831.23,4327.17 3831.23,4381.04 3859.96,4409.77 4347.13,4409.77 4361.3,4395.61 4382.28,4395.61 4415.74,4429.07 4527.1,4429.07 4541.64,4443.61 4541.64,4470.7 v1(4556.94,4486) 4556.94,4524.29 4604.62,4571.97 4705.61,4571.97 4743.42,4534.16 4767.19,4534.16 4791.65,4509.7 4878.6,4509.7 4888.65,4499.65 4948.2,4499.65 4958.26,4509.72 4958.26,4565.39 4966.01,4573.14 5059.53,4573.14 J3.3@5090.29,4542.38 5169.88,4462.79 5169.88,4247.04 5205.89,4211.03 v1(5205.89,4161.98) 5226.47,4141.41 5226.47,4092.33 5316.67,4002.12 5316.67,3875.94 5349.69,3842.92 v1(5420.37,3842.92)
  Bottom Layer w5.5: R7.1@3944.52,3878.69 3944.52,3875.62 v1(3961.99,3858.15) ; J3.3@5090.29,4542.38 5122.21,4510.46 R101.2@5212.35,4510.46 ; R57.1@5180.56,4161.98 v1(5205.89,4161.98) ; R71.2@5383.33,3780.67 5383.86,3781.2 5404.84,3781.2 5420.37,3796.73 v1(5420.37,3842.92)
AR_SOP0: R83.2 R158.2 R159.1 R174.2 | length 105.5
  Bottom Layer w5.5: R159.1@4223.5,4089.12 4223.5,4089.91 4227.05,4093.46 4236,4093.46 4239.22,4096.68 R158.2@4239.22,4119.6 4241.84,4122.21 4266.49,4122.21 R174.2@4269.1,4124.82 4268.19,4125.73 4268.19,4154.39 R83.2@4267.28,4155.3
AR_SOP1: R84.2 R170.2 R171.1 | length 100.6
  Bottom Layer w5.5: R84.2@4130.41,3922.4 4130.41,3933.54 R170.2@4143.32,3946.46 4143.32,3958.65 4148.32,3963.64 4176.89,3963.64 R171.1@4193.42,3980.18
AR_SOP2: R85.2 R172.2 R176.2 | length 111
  Bottom Layer w5.5: R85.2@4365.96,4224.99 4396.89,4224.99 4408.3,4213.57 4408.3,4189.48 R176.2@4400.62,4181.8 4401.11,4181.32 R172.2@4401.11,4153.05
AR_SPICLK1: R75.2 R136.2 U2.D2 | length 3190
  Top Layer w5.5: U2.D2@3883.25,3905.39 v1(3899,3889.64) ; R136.2@6248.02,4241 6248.02,4230.98 6252,4227 v1(6273,4227)
  Sig1 w4.2: v1(4524,3826) 4581.48,3826 4608.47,3799.01 4608.47,3787.53 4624.78,3771.22 4772.81,3771.22 4797.6,3796 4797.6,3816.6 4846.6,3865.6 4846.6,3873.19 4938.65,3965.25 5055.93,3965.25 5123.42,3897.75 5123.42,3847.22 5135.92,3834.72 5135.92,3722.08 5148.37,3709.63 5166.58,3709.63 5196.33,3739.38 5500.17,3739.38 5637.8,3877.01 5637.8,3944.8 5651.7,3958.7 5695.8,3958.7 5729.1,3992 6231,3992 6282,4043 6282,4218 v1(6273,4227)
  Sig2 w4.2: v1(3899,3889.64) 3940.35,3889.64 3956.55,3873.45 3999.83,3873.45 3999.93,3873.34 4050.25,3873.34 4050.36,3873.45 4346.28,3873.45 4361.54,3858.19 4494.81,3858.19 4523,3830 4523,3827 v1(4524,3826)
  Bottom Layer w5.5: R75.2@3875.37,3896.78 3891.86,3896.78 v1(3899,3889.64)
AR_SYNC_IN: RA8.8 U2.U12 | length 931.4
  Top Layer w5.5: U2.U12@4292.7,4220.35 v1(4308.45,4204.6)
  Sig2 w4.2: v1(4308.45,4204.6) 4344.14,4204.6 4367.21,4181.54 4397.56,4181.54 4415.59,4199.56 4550.34,4199.56 4560.42,4209.65 4717.42,4209.65 4759.2,4251.43 4759.2,4251.65 4780.03,4272.48 4891.89,4272.48 4996.41,4167.96 4996.41,4093.05 v1(4971.61,4068.25)
  Bottom Layer w5.5: RA8.8@4952.69,4072.25 4967.61,4072.25 v1(4971.61,4068.25)
AR_SYNC_OUT_SOP1: R84.1 RA8.7 U2.M3 | length 1135.8
  Top Layer w5.5: v1(4119.47,3952.63) U2.M3@4135.22,3936.89
  Sig2 w4.2: v1(4119.47,3952.63) 4167.16,4000.33 4313.89,4000.33 4325.09,3989.12 4325.09,3946.41 4377.92,3893.59 4525.16,3893.59 4545.46,3873.29 4650.44,3873.29 4695.78,3918.63 4821.98,3918.63 4947.18,4043.83 4947.18,4067.33 v1(4973.31,4093.46)
  Bottom Layer w5.5: R84.1@4109.37,3922.4 4109.37,3942.53 v1(4119.47,3952.63) ; RA8.7@4952.69,4088 4967.85,4088 v1(4973.31,4093.46)
AR_TCK: RA4.2 U2.T3 | length 552.9
  Top Layer w5.5: v1(4245.46,3952.63) U2.T3@4261.2,3936.89 ; v1@4532.81,3949.39 v1(4535.35,3946.85) 4544.91,3937.29 4573.76,3937.29 4579.07,3931.99 4604.64,3931.99 4612.69,3940.04 RA4.2@4612.69,3946.67
  Bottom Layer w5.5: v1(4245.46,3952.63) 4246.46,3951.63 4335.33,3951.63 4388.35,4004.65 4388.35,4024.15 4414.2,4050 4514.75,4050 4532.92,4031.83 4532.92,3949.29 v1(4535.35,3946.85)
AR_TDI: RA4.4 U2.U9 | length 705.9
  Top Layer w5.5: U2.U9@4292.7,4125.86 4307.32,4111.24 4353.47,4111.24 4361.57,4103.14 4361.57,4065.53 4367.7,4059.39 4391,4059.39 4401.46,4048.93 4401.46,4040.6 4393.56,4032.7 4363.3,4032.7 4357.05,4026.45 4357.05,4000.45 4361.5,3996 4389.59,3996 4401.46,3984.13 4401.46,3952.48 4437.05,3916.9 4536.15,3916.9 4599.89,3853.17 4624.33,3853.17 4656.39,3885.22 4656.39,3934.47 RA4.4@4644.19,3946.67
AR_TDO_SOP0: R83.1 RA4.3 U2.U10 | length 595.3
  Top Layer w5.5: U2.U10@4292.7,4157.36 v1(4308.45,4141.61) ; v1(4559.05,3919.14) 4617.44,3919.14 4628.44,3930.13 RA4.3@4628.44,3946.67
  Sig2 w4.2: v1(4308.45,4141.61) 4332.17,4117.89 4378.11,4117.89 4436.42,4059.59 4541.61,4059.59 4588.41,4012.78 4588.41,3924.98 4582.57,3919.14 v1(4559.05,3919.14)
  Bottom Layer w4.2: R83.1@4288.32,4155.3 4301.27,4155.3 4308.45,4148.13 4308.45,4145.34 v1(4308.45,4141.61)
